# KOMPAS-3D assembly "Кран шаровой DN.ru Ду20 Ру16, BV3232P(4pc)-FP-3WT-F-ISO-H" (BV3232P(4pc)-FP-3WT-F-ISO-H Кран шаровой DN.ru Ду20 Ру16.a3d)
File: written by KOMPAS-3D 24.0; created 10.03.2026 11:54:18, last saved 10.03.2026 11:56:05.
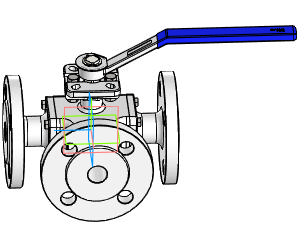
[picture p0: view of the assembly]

Document properties: Автор: R2D2; Полное имя файла: E:\Работа\Зайцев\BV3232P(4pc)-FP-3WT-F-ISO-H Кран шаровой DN.ru Ду15-100 Ру16\DN20\исходные материалы\BV3232P(4pc)-FP-3WT-F-ISO-H Кран шаровой DN.ru Ду20 Ру16.a3d

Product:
- Component [assembly]: Сборка1  | qty 1  | pos. 1  | Масса: 4.915073; Автор: R2D2; source file: dn20_3d_step.a3d
- Part/product: Кран шаровой DN.ru Ду20 Ру16  | designation BV3232P(4pc)-FP-3WT-F-ISO-H
    Масса: 4.5
    Раздел спецификации: Прочие изделия
    Примечание: D160-36347

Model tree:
1. Эскиз:1  (labels: Грань.Твердое тело1; Ребро.Твердое тело1)
2. Элемент выдавливания:1  (labels: Грань.Твердое тело1; Твердое тело1)
     Расстояние 2 = 0.01

Referenced files in E:\Работа\Зайцев\BV3232P(4pc)-FP-3WT-F-ISO-H Кран шаровой DN.ru Ду15-100 Ру16\DN20\исходные материалы\: dn20_3d_step.a3d
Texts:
  BV3232P(4pc)-FP-3WT-F-ISO-H
  Сборка1 Сборка1
  Ось Z.Начало координат
  Ось Y.Начало координат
